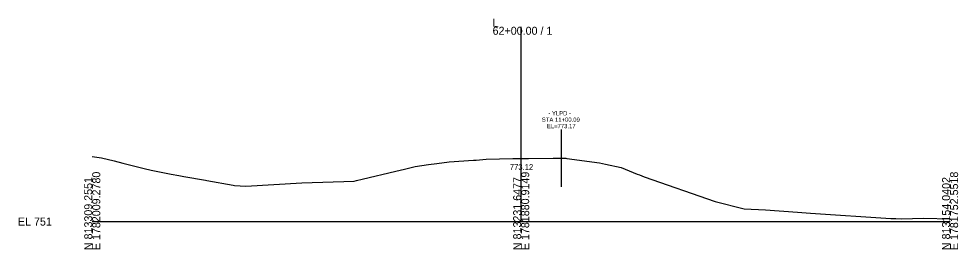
# Model space of a CAD drawing. Extents: x -26 to 7903, y -10 to 9573.
# Drawn here: x 2974.3 to 3302.8, y 2990.3 to 3071.1 of the extents above; entities that cross this region are included whole.
import ezdxf

# ---------------------------------------------------------------- set-up
doc = ezdxf.new("R2010")
doc.units = 0
for name, color, linetype in [('Exist Cross Section Cell', 7, 'Continuous'), ('Exist XS Center Line Elevation Label', 7, 'Continuous'), ('Exist XS Ground Line', 7, 'Continuous'), ('Prop XS Vertical Lines Alignments', 7, 'Continuous')]:
    doc.layers.add(name, color=color, linetype=linetype)

msp = doc.modelspace()

# ---------------------------------------------------------------- linework, layer by layer
at = {"layer": 'Exist Cross Section Cell'}
for p, q in [((3150, 3000), (3150, 3068.25)), ((3000, 3000), (3150, 3000)), ((3150, 3000), (3300, 3000))]:
    msp.add_line(p, q, dxfattribs=at)
at = {"layer": 'Exist XS Ground Line'}
for p, q in [((3000, 3022.75), (3003.25, 3022.33)), ((3003.25, 3022.33), (3007.68, 3021.28)), ((3007.68, 3021.28), (3010.75, 3020.47)), ((3010.75, 3020.47), (3018.19, 3018.61)), ((3109.23, 3018.39), (3112.97, 3019.25)), ((3112.97, 3019.25), (3117.61, 3019.99)), ((3117.61, 3019.99), (3120.45, 3020.38)), ((3120.45, 3020.38), (3124.78, 3020.9)), ((3124.78, 3020.9), (3133.35, 3021.5)), ((3133.35, 3021.5), (3133.76, 3021.53)), ((3133.76, 3021.53), (3134.26, 3021.57)), ((3134.26, 3021.57), (3137.74, 3021.82)), ((3137.74, 3021.82), (3147.08, 3022.05)), ((3147.08, 3022.05), (3149.38, 3022.11)), ((3149.38, 3022.11), (3150, 3022.12)), ((3150, 3022.12), (3152.54, 3022.14)), ((3152.54, 3022.14), (3161.17, 3022.24)), ((3161.17, 3022.24), (3165.63, 3022.18)), ((3165.63, 3022.18), (3165.93, 3022.14)), ((3165.93, 3022.14), (3177.45, 3020.58)), ((3177.45, 3020.58), (3179.51, 3020.13)), ((3179.51, 3020.13), (3184.98, 3018.99)), ((3018.19, 3018.61), (3020.65, 3018.01)), ((3020.65, 3018.01), (3027.65, 3016.63)), ((3027.65, 3016.63), (3030.32, 3016.1)), ((3030.32, 3016.1), (3031.97, 3015.83)), ((3094.44, 3014.8), (3106.22, 3017.67)), ((3106.22, 3017.67), (3109.23, 3018.39)), ((3184.98, 3018.99), (3190.51, 3016.66)), ((3190.51, 3016.66), (3191.34, 3016.32)), ((3191.34, 3016.32), (3193.07, 3015.71)), ((3031.97, 3015.83), (3039.63, 3014.46)), ((3039.63, 3014.46), (3040.09, 3014.38)), ((3040.09, 3014.38), (3049.26, 3012.71)), ((3049.26, 3012.71), (3049.77, 3012.64)), ((3053.66, 3012.4), (3073.3, 3013.59)), ((3073.3, 3013.59), (3091.58, 3014.14)), ((3091.58, 3014.14), (3092.38, 3014.34)), ((3092.38, 3014.34), (3094.44, 3014.8)), ((3193.07, 3015.71), (3217.87, 3007.09)), ((3049.77, 3012.64), (3053.66, 3012.4)), ((3217.87, 3007.09), (3228.03, 3004.41)), ((3228.03, 3004.41), (3235.44, 3004.15)), ((3235.44, 3004.15), (3246.58, 3003.34)), ((3246.58, 3003.34), (3251.21, 3003)), ((3251.21, 3003), (3279.29, 3001.08)), ((3279.29, 3001.08), (3281.05, 3001.02)), ((3281.05, 3001.02), (3282.93, 3000.95)), ((3282.93, 3000.95), (3290.81, 3001.2)), ((3290.81, 3001.2), (3300, 3000.92))]:
    msp.add_line(p, q, dxfattribs=at)
at = {"layer": 'Prop XS Vertical Lines Alignments'}
msp.add_line((3163.98, 3032.2), (3163.98, 3012.12), dxfattribs=at)

# ---------------------------------------------------------------- texts
at = {"layer": 'Exist Cross Section Cell'}
for s, p in [('L', (3140, 3068.25)), ('62+00.00 / 1', (3140, 3065.45)), ('EL 751', (2974, 2998.6))]:
    msp.add_text(s, height=2.8, dxfattribs=at).set_placement(p)
for s, p in [('E 1782009.2780', (3002.8, 2990)), ('E 1781880.9149', (3152.8, 2990)), ('E 1781752.5518', (3302.8, 2990)), ('N 813309.2551', (3000, 2990)), ('N 813231.6477', (3150, 2990)), ('N 813154.0402', (3300, 2990))]:
    msp.add_text(s, height=2.8, rotation=90, dxfattribs=at).set_placement(p)
at = {"layer": 'Exist XS Center Line Elevation Label'}
msp.add_text('773.12', height=2, dxfattribs=at).set_placement((3146.03, 3018.12))
at = {"layer": 'Prop XS Vertical Lines Alignments'}
for s, p in [('STA 11+00.09', (3157.22, 3034.95)), ('- YLPD -', (3159.49, 3037.2)), ('EL=773.17', (3158.97, 3032.7))]:
    msp.add_text(s, height=1.5, dxfattribs=at).set_placement(p)

doc.saveas('drawing.dxf')
